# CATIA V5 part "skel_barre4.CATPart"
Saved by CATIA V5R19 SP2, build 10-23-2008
Part number: skel_barre4
Bounding box of the stored display mesh (mm): x 0 to 20, y 0 to 9.108, z 0 to 17.806
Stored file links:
  E:\TRAVAIL\IAO\skel_barre4.CATPart
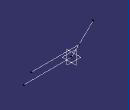
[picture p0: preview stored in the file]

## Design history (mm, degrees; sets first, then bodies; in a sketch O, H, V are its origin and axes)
Body1 (main body)
  Point1 "Point.F": stored without definition
  Point2 "Point.S": stored without definition
  Line1 "barre4": type PtPt, FirstPoint Point1, SecondPoint Point2
  Plane1 "Plan_ref": stored without definition
  Point3 "Point.F": stored without definition
  Line2 "axe_pivot_barre4_bati": type Normal, RefPoint Point3, RefSkin Plane1, Start 0, End 20
  Plane2 "Plan_ref": stored without definition
  Point4 "Point.D": stored without definition
  Line3 "axe_pivot_barre4_barre3": type Normal, RefPoint Point4, RefSkin Plane2, Start 0, End 20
